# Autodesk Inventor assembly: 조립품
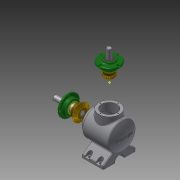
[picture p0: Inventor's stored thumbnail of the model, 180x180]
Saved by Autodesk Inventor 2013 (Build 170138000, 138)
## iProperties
Created: 2017-04
Part Number: 조립품
Document SubType Name: Assembly
Designer: Administrator
Author: Administrator
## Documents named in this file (13)
- C:\Users\Administrator\Desktop\470408V1007\조립품.iam
- C:\Users\Administrator\Desktop\470408V1007\1. 본체.ipt
- C:\Users\Administrator\Desktop\470408V1007\메인 축.ipt
- 메인 축.ipt
- C:\Users\Administrator\Desktop\470408V1007\커버.ipt
- C:\Users\Administrator\Desktop\470408V1007\베어링 6203.ipt
- C:\Users\Administrator\Desktop\470408V1007\오일실 17 32 8.ipt
- C:\Users\Administrator\Desktop\470408V1007\키 5x5.ipt
- C:\Users\Administrator\Desktop\470408V1007\메인 베벨기어.ipt
- C:\Users\Administrator\Desktop\470408V1007\서브 베벨기어.ipt
- C:\Users\Administrator\Desktop\470408V1007\서브 축.ipt
- 서브 축.ipt
- C:\Users\Administrator\Desktop\470408V1007\키 4x4.ipt
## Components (1 placed, 1 different names)
1. 1. 본체:1
